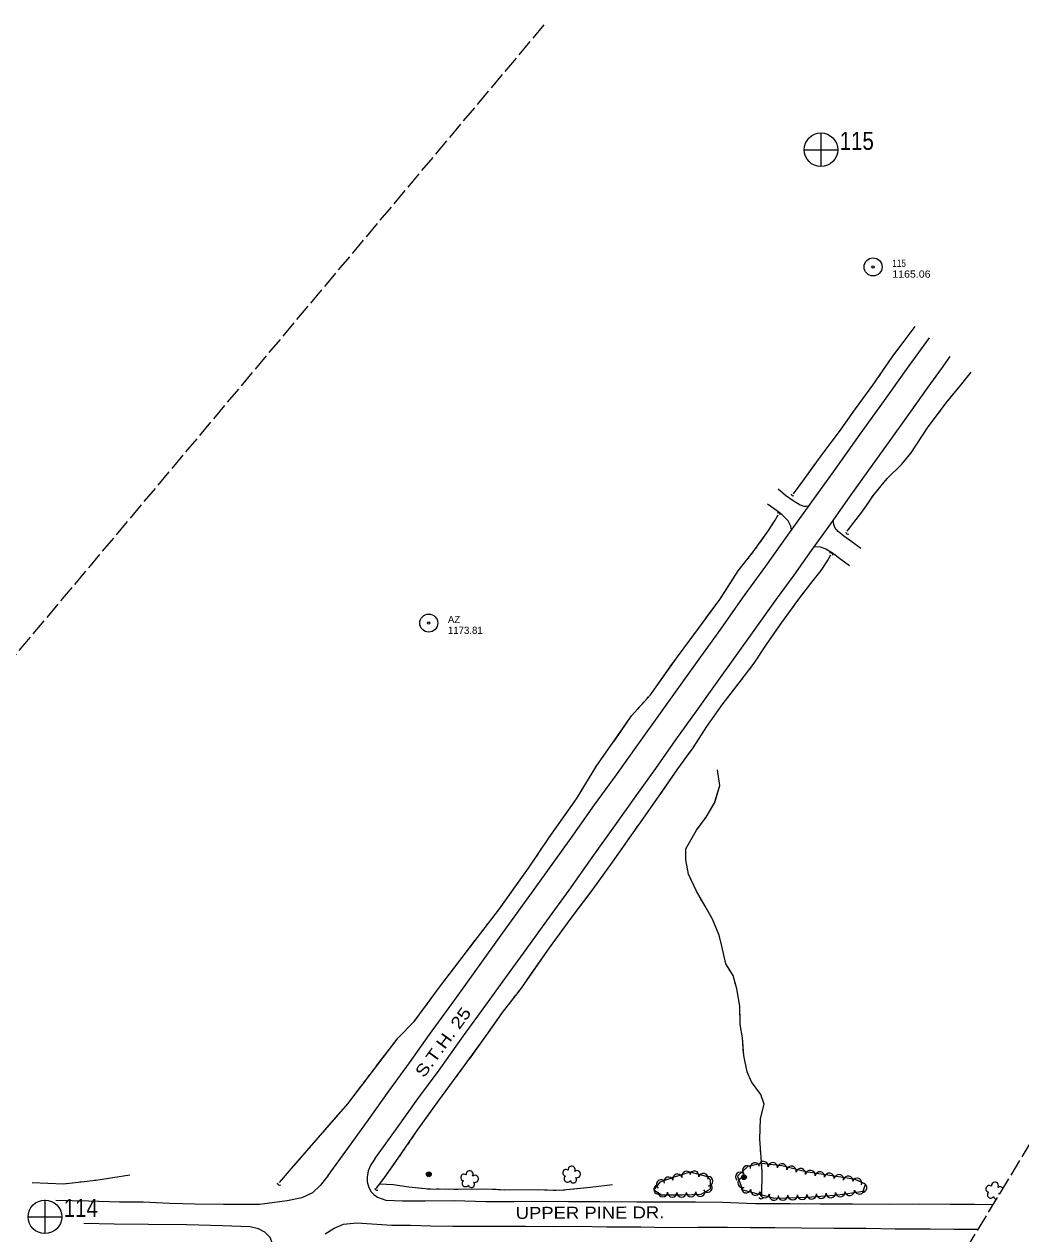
# Model space of a CAD drawing. Extents: x 299912 to 302269, y 50501 to 52727.
# Drawn here: x 300777 to 301607, y 51133 to 52140 of the extents above; entities that cross this region are included whole.
import ezdxf

# ---------------------------------------------------------------- set-up
doc = ezdxf.new("R2010")
doc.units = 0
doc.header["$LTSCALE"] = 2.4
doc.linetypes.add('LONG_DASHED', pattern=[7.5, 6, -1.5])
for name, color, linetype, lineweight in [('11', 7, 'Continuous', 25), ('14', 7, 'Continuous', 13), ('15', 7, 'Continuous', 13), ('17', 7, 'LONG_DASHED', 13), ('18', 7, 'Continuous', 13), ('19', 7, 'Continuous', 13), ('4', 7, 'Continuous', 13), ('6', 7, 'Continuous', 13)]:
    doc.layers.add(name, color=color, linetype=linetype, lineweight=lineweight)

msp = doc.modelspace()

# ---------------------------------------------------------------- linework, layer by layer
at = {"layer": '11'}
for points in [[(301030.007, 51181.149), (301047.014, 51204.403), (301063.672, 51227.601), (301080.566, 51251.235), (301097.734, 51274.915), (301114.585, 51298.443), (301135.571, 51327.45), (301153.998, 51353.028), (301175.685, 51383.222), (301194.525, 51409.49), (301211.625, 51433.285), (301232.183, 51461.909), (301252.093, 51489.845), (301270.355, 51515.057), (301288.212, 51539.974), (301306.971, 51566.236), (301323.759, 51589.729), (301339.213, 51611.228), (301357.233, 51636.354), (301375.434, 51662.035), (301394.708, 51688.805), (301413.138, 51714.567), (301431.636, 51740.489), (301452.429, 51769.443), (301473.451, 51798.854), (301493.551, 51826.891), (301511.926, 51852.541), (301531.073, 51879.143)], [(301068.854, 51194.99), (301086.974, 51220.113), (301104.786, 51244.929), (301122.378, 51268.943), (301142.82, 51297.37), (301161.297, 51323.08), (301179.46, 51347.984), (301195.045, 51369.431), (301212.341, 51393.305), (301230.758, 51418.776), (301250.082, 51446.051), (301268.963, 51472.323), (301286.717, 51497.399), (301303.095, 51520.241), (301319.863, 51544.01), (301336.981, 51567.976), (301351.404, 51588.279), (301370.357, 51614.741), (301386.323, 51637.108), (301403.784, 51661.391), (301418.292, 51681.277), (301432.749, 51701.911), (301448.871, 51724.104), (301463.212, 51744.317), (301479.209, 51766.758), (301496.984, 51791.456), (301514.628, 51815.931), (301530.056, 51837.899), (301541.095, 51853.142), (301548.391, 51863.553)], [(301068.854, 51194.99), (301065.444, 51189.953), (301063.437, 51184.92), (301062.592, 51179.821), (301062.381, 51175.94), (301063.58, 51171.87), (301065.5, 51167.886), (301067.97, 51165.401), (301071.23, 51163.033), (301074.098, 51162.001), (301077.997, 51160.671), (301092.055, 51160.116), (301110.856, 51159.999), (301135.177, 51160.188), (301161.367, 51159.458), (301185.028, 51159.394), (301208.788, 51159.576), (301230.116, 51159.482), (301256.401, 51159.431), (301287.257, 51159.108), (301312.985, 51159.252), (301336.181, 51159.101), (301358.657, 51158.812), (301386.076, 51157.897), (301414.94, 51157.726), (301439.969, 51157.378), (301466.928, 51157.513), (301497.572, 51157.317), (301523.037, 51157.547), (301548.404, 51157.168), (301568.532, 51157.153), (301584.04, 51157.001)], [(301030.007, 51181.149), (301023.253, 51172.718), (301017.043, 51166.584), (301008.163, 51162.486), (300995.866, 51160.121), (300972.836, 51157.009), (300942.884, 51156.811), (300919.181, 51157.333), (300897.924, 51157.791), (300875.705, 51158.909), (300856.054, 51158.98), (300830.211, 51159.603), (300802.901, 51160.158)], [(300937.665, 51052.35), (300948.96, 51067.795), (300962.34, 51086.522), (300973.837, 51102.347), (300980.826, 51112.339), (300983.524, 51117.902), (300983.699, 51124.492), (300981.529, 51129.444), (300977.355, 51133.747), (300971.926, 51136.725), (300965.099, 51138.361), (300942.042, 51139.1), (300912.271, 51139.909), (300880.328, 51140.137), (300851.613, 51140.546), (300826.248, 51141.024)], [(301027.487, 51132.484), (301035.101, 51137.124), (301042.714, 51140.527), (301053.832, 51141.717), (301070.425, 51140.556), (301082.862, 51139.682), (301098.541, 51139.579), (301115.587, 51139.262), (301133.98, 51138.959), (301155.725, 51139.01), (301173.969, 51138.84), (301194.485, 51138.925), (301217.475, 51138.683), (301238.152, 51138.78), (301262.162, 51138.455), (301290.563, 51138.275), (301313.431, 51137.861), (301337.789, 51137.928), (301362.93, 51137.939), (301381.996, 51137.771), (301402.223, 51137.859), (301424.429, 51137.516), (301451.548, 51137.112), (301478.4, 51137.154), (301502.642, 51136.595), (301531.587, 51136.55), (301551.826, 51136.439), (301571.518, 51136.387)]]:
    msp.add_lwpolyline(points, dxfattribs=at)
at = {"layer": '14'}
for centre, radius in [((301113.85, 51182.141), 2.018), ((301113.838, 51182.147), 1.518), ((301113.873, 51182.127), 1.008), ((301113.868, 51182.136), 0.502), ((301376.502, 51179.703), 2.018), ((301376.49, 51179.709), 1.518), ((301376.525, 51179.689), 1.008), ((301376.52, 51179.698), 0.502)]:
    msp.add_circle(centre, radius, dxfattribs=at)
at = {"layer": '15'}
for centre, radius, start, end in [((301417.578, 51749.26), 1.803, 184.36862, 290.60818), ((301404.821, 51731.319), 1.855, 4.88223, 111.1218), ((301463.173, 51717.358), 1.817, 184.27214, 290.51171), ((301448.525, 51697.901), 2.04, 4.49441, 110.73398), ((300989.781, 51175.348), 2.295, 186.25561, 292.49518), ((301070.67, 51170.633), 1.832, 182.56024, 288.7998), ((301390.989, 51164.055), 2.372, 209.35363, 315.59319)]:
    msp.add_arc(centre, radius, start, end, dxfattribs=at)
at = {"layer": '17'}
for points in [[(301404.91, 51753.214), (301411.012, 51748.014), (301417.539, 51743.527), (301423.306, 51740.024), (301426.521, 51738.909), (301428.262, 51738.88), (301430.681, 51739.151)], [(301416.104, 51718.723), (301415.587, 51722.216), (301413.326, 51726.549), (301408.449, 51731.612), (301403.696, 51735.293), (301396.168, 51740.426)], [(301474.029, 51703.408), (301466.45, 51708.994), (301459.792, 51713.789), (301454.976, 51717.791), (301452.277, 51721.069), (301451.302, 51723.498), (301451.001, 51727.107)], [(301435.156, 51705.224), (301439.996, 51704.803), (301444.756, 51703.158), (301450.39, 51699.995), (301457.172, 51694.626), (301464.351, 51689.387)]]:
    msp.add_lwpolyline(points, dxfattribs=at)
at = {"layer": '18'}
for points in [[(301428.219, 51184.021), (301408.042, 51189.031), (301391.174, 51191.136), (301379.762, 51188.531), (301371.027, 51180.507), (301375.319, 51169.195), (301402.093, 51162.251), (301429.118, 51163.082), (301451.908, 51164.736), (301461.046, 51165.728), (301475.847, 51167.989), (301477.689, 51174.007), (301469.18, 51177.815), (301460.863, 51179.272)], [(301331.755, 51183.846), (301318.456, 51179.677), (301306.324, 51175.553), (301301.506, 51169.217), (301307.732, 51165.104), (301325.015, 51164.869), (301340.746, 51165.56), (301348.652, 51170.07), (301348.752, 51177.208), (301346.514, 51179.799), (301343.475, 51180.866)]]:
    msp.add_lwpolyline(points, close=True, dxfattribs=at)
for centre, radius, start, end in [((301232.929, 51186.01), 2.974, 328.44813, 189.68202), ((301379.299, 51185.26), 4.004, 42.57835, 222.56303), ((301385.545, 51187.701), 4.004, 12.86617, 192.85084), ((301392.656, 51188.839), 4.004, 352.89435, 172.87903), ((301400.602, 51187.848), 4.004, 352.89435, 172.87903), ((301408.285, 51186.811), 4.004, 346.06299, 166.04767), ((301416.056, 51184.882), 4.004, 346.06299, 166.04767), ((301143.23, 51179.471), 2.777, 51.41902, 259.19202), ((301147.893, 51182.142), 2.974, 328.44813, 189.68202), ((301152.307, 51178.296), 2.975, 246.09895, 129.07222), ((301228.266, 51183.339), 2.777, 51.41902, 259.19202), ((301229.462, 51178.421), 2.783, 128.09604, 329.10709), ((301234.416, 51177.481), 2.611, 190.80419, 48.73679), ((301237.343, 51182.164), 2.975, 246.09895, 129.07222), ((301313.686, 51175.88), 3.936, 18.78197, 198.76665), ((301321.106, 51178.349), 3.936, 17.41294, 197.39762), ((301328.616, 51180.703), 3.936, 17.41294, 197.39762), ((301335.061, 51180.88), 3.936, 345.74159, 165.72627), ((301342.688, 51178.941), 3.936, 345.74159, 165.72627), ((301346.679, 51176.3), 3.936, 269.20503, 89.18971), ((301373.402, 51179.843), 4.004, 42.57835, 222.56303), ((301375.366, 51174.979), 4.004, 110.78541, 290.77009), ((301423.828, 51182.952), 4.004, 346.06299, 166.04767), ((301431.879, 51181.371), 4.004, 351.73043, 171.7151), ((301439.803, 51180.218), 4.004, 351.73043, 171.7151), ((301447.727, 51179.065), 4.004, 351.73043, 171.7151), ((301455.651, 51177.913), 4.004, 351.73043, 171.7151), ((301463.501, 51176.682), 4.004, 350.07122, 170.0559), ((301470.705, 51174.837), 4.004, 335.8979, 155.88258), ((301144.426, 51174.553), 2.783, 128.09604, 329.10709), ((301149.38, 51173.613), 2.611, 190.80419, 48.73679), ((301305.367, 51169.528), 3.936, 106.55824, 286.54292), ((301307.482, 51173.673), 3.936, 52.7577, 232.74238), ((301346.182, 51171.032), 3.936, 209.71038, 29.69506), ((301378.378, 51170.567), 4.004, 165.46801, 345.45269), ((301386.129, 51168.557), 4.004, 165.46801, 345.45269), ((301464.642, 51168.397), 4.004, 188.69302, 8.67769), ((301472.558, 51169.607), 4.004, 188.69302, 8.67769), ((301474.965, 51170.973), 4.004, 282.98927, 102.97394), ((301580.976, 51169.924), 2.777, 51.41902, 259.19202), ((301585.639, 51172.595), 2.974, 328.44813, 189.68202), ((301590.053, 51168.749), 2.975, 39.88291, 129.07222), ((301308.873, 51167.148), 3.936, 179.22865, 359.21333), ((301316.743, 51167.041), 3.936, 179.22865, 359.21333), ((301324.612, 51166.934), 3.936, 179.22865, 359.21333), ((301332.357, 51167.253), 3.936, 182.52282, 2.5075), ((301340.219, 51167.599), 3.936, 182.52282, 2.5075), ((301393.879, 51166.546), 4.004, 165.46801, 345.45269), ((301401.63, 51164.536), 4.004, 165.46801, 345.45269), ((301409.011, 51164.56), 4.004, 181.76891, 1.75359), ((301417.015, 51164.807), 4.004, 181.76891, 1.75359), ((301425.018, 51165.053), 4.004, 181.76891, 1.75359), ((301432.926, 51165.46), 4.004, 184.15866, 4.14334), ((301440.912, 51166.039), 4.004, 184.15866, 4.14334), ((301448.899, 51166.619), 4.004, 184.15866, 4.14334), ((301456.794, 51167.374), 4.004, 186.2033, 6.18797), ((301582.172, 51165.006), 2.783, 128.09604, 329.10709), ((301587.126, 51164.066), 2.611, 190.80419, 261.98746), ((301587.126, 51164.066), 2.611, 35.45675, 48.73679), ((301590.053, 51168.749), 2.975, 246.09895, 257.56129)]:
    msp.add_arc(centre, radius, start, end, dxfattribs=at)
at = {"layer": '19'}
for p, q in [((301493.02, 51852.803), (301494.239, 51854.579)), ((301496.677, 51858.131), (301497.896, 51859.907)), ((301489.363, 51847.474), (301490.582, 51849.25)), ((301538.974, 51816.656), (301540.238, 51818.337)), ((301542.765, 51821.701), (301544.028, 51823.383)), ((301535.184, 51811.61), (301536.448, 51813.292)), ((301442.6, 51782.938), (301443.887, 51784.665)), ((301446.461, 51788.12), (301447.748, 51789.848)), ((301438.764, 51777.736), (301440.036, 51779.475)), ((301490.957, 51755.731), (301492.306, 51757.344)), ((301483.097, 51745.876), (301484.273, 51747.618)), ((301486.908, 51750.892), (301488.257, 51752.505)), ((301386.324, 51703.519), (301387.436, 51705.098)), ((301379.248, 51694.344), (301380.455, 51695.852)), ((301382.87, 51698.867), (301384.078, 51700.375)), ((301424.675, 51664.554), (301425.913, 51666.167)), ((301428.387, 51669.392), (301429.624, 51671.005)), ((301421.039, 51659.66), (301422.225, 51661.311)), ((301341.407, 51640.717), (301342.554, 51642.272)), ((301334.501, 51631.406), (301335.655, 51632.956)), ((301299.465, 51582.831), (301315.648, 51605.704)), ((301381.382, 51603.09), (301382.623, 51604.7)), ((301373.936, 51593.431), (301375.177, 51595.041)), ((301377.659, 51598.26), (301378.9, 51599.87)), ((301291.864, 51574.091), (301293.156, 51575.527)), ((301295.74, 51578.401), (301297.032, 51579.837)), ((301287.988, 51569.78), (301289.28, 51571.217)), ((301330.34, 51532.196), (301331.537, 51533.839)), ((301326.749, 51527.268), (301327.946, 51528.911)), ((301246.941, 51511.362), (301247.936, 51513.018)), ((301249.927, 51516.329), (301250.922, 51517.985)), ((301243.955, 51506.395), (301244.95, 51508.05)), ((301346.697, 51482.534), (301347.641, 51484.17)), ((301349.53, 51487.442), (301350.474, 51489.078)), ((301287.007, 51470.741), (301288.175, 51472.404)), ((301343.62, 51477.788), (301344.756, 51479.297)), ((301280.002, 51460.761), (301281.169, 51462.425)), ((301283.505, 51465.751), (301284.672, 51467.414)), ((301207.039, 51452.095), (301208.114, 51453.7)), ((301200.583, 51442.467), (301201.659, 51444.071)), ((301203.811, 51447.281), (301204.887, 51448.886)), ((301336.075, 51419.707), (301335.275, 51421.417)), ((301338.75, 51414.716), (301337.809, 51416.354)), ((301341.573, 51409.802), (301340.632, 51411.44)), ((301235.894, 51399.876), (301237.115, 51401.5)), ((301239.557, 51404.748), (301240.779, 51406.373)), ((301161.969, 51389.338), (301163.14, 51390.875)), ((301232.247, 51394.99), (301233.452, 51396.627)), ((301154.943, 51380.117), (301156.114, 51381.654)), ((301158.456, 51384.727), (301159.627, 51386.264)), ((301195.639, 51343.723), (301212.442, 51367.933)), ((301365.473, 51350.838), (301364.479, 51352.444)), ((301192.162, 51338.714), (301193.321, 51340.384)), ((301367.959, 51345.804), (301367.456, 51347.624)), ((301369.466, 51340.343), (301368.964, 51342.164)), ((301184.729, 51329.059), (301185.982, 51330.658)), ((301188.487, 51333.855), (301189.74, 51335.454)), ((301108.402, 51318.431), (301109.546, 51319.987)), ((301111.835, 51323.1), (301112.979, 51324.656)), ((301115.268, 51327.769), (301116.412, 51329.325)), ((301070.318, 51272.376), (301087.393, 51294.58)), ((301140.502, 51268.298), (301141.709, 51269.933)), ((301144.118, 51273.205), (301145.313, 51274.848)), ((301377.276, 51276.815), (301376.87, 51278.66)), ((301378.494, 51271.281), (301378.088, 51273.126)), ((301059.751, 51258.571), (301060.924, 51260.106)), ((301063.269, 51263.176), (301064.441, 51264.711)), ((301136.883, 51263.394), (301138.089, 51265.029)), ((301380.023, 51265.844), (301379.308, 51267.592)), ((301021.67, 51212.383), (301039.96, 51233.601)), ((301096.582, 51207.307), (301097.729, 51208.983)), ((301010.291, 51199.235), (301011.556, 51200.695)), ((301014.088, 51203.614), (301015.353, 51205.074)), ((301089.702, 51197.254), (301090.849, 51198.929)), ((301093.142, 51202.28), (301094.289, 51203.956)), ((301390.095, 51205.686), (301389.952, 51207.569)), ((301390.527, 51200.037), (301390.383, 51201.92)), ((301390.958, 51194.388), (301390.814, 51196.271)), ((300817.015, 51175.056), (300819.055, 51175.288)), ((300823.136, 51175.751), (300825.176, 51175.982)), ((300829.257, 51176.445), (300831.297, 51176.676)), ((301120.198, 51169.897), (301122.63, 51169.882)), ((301127.494, 51169.851), (301129.927, 51169.835)), ((301210.17, 51169.08), (301212.6, 51169.017)), ((301217.459, 51168.893), (301219.889, 51168.83)), ((301224.738, 51168.914), (301227.151, 51169.172))]:
    msp.add_line(p, q, dxfattribs=at)
for points in [[(301417.935, 51748.937), (301426.349, 51760.761), (301440.899, 51780.655), (301457.447, 51802.865), (301469.365, 51819.834), (301483.942, 51839.575), (301499.994, 51862.965), (301510.103, 51876.365), (301519.094, 51888.425)], [(301500.355, 51863.444), (301510.103, 51876.365), (301519.094, 51888.425)], [(301462.635, 51717.891), (301475.648, 51734.836), (301484.709, 51748.264), (301495.998, 51761.756), (301508.13, 51773.69), (301515.818, 51783.211), (301529.456, 51803.985), (301545.058, 51824.754), (301558.037, 51840.806), (301565.774, 51850.43)], [(301468.547, 51818.669), (301469.365, 51819.834), (301483.942, 51839.575), (301486.925, 51843.922)], [(301546.625, 51826.692), (301558.037, 51840.806), (301565.774, 51850.43)], [(301450.322, 51793.303), (301457.447, 51802.865), (301468.547, 51818.669)], [(301515.621, 51782.966), (301515.818, 51783.211), (301529.456, 51803.985), (301532.657, 51808.246)], [(301417.935, 51748.937), (301426.349, 51760.761), (301436.221, 51774.258)], [(301495.005, 51760.57), (301495.998, 51761.756), (301508.13, 51773.69), (301515.621, 51782.966)], [(301462.635, 51717.891), (301475.648, 51734.836), (301480.746, 51742.391)], [(300989.393, 51175.16), (300999.521, 51186.814), (301018.108, 51208.251), (301046.288, 51240.942), (301066.826, 51267.834), (301088.285, 51295.74), (301101.716, 51309.337), (301124.372, 51340.151), (301145.396, 51367.586), (301172.671, 51403.384), (301197.002, 51437.125), (301214.19, 51462.762), (301237.092, 51494.977), (301253.783, 51522.745), (301267.096, 51541.255), (301282.839, 51564.054), (301298.509, 51581.48), (301321.055, 51613.347), (301338.646, 51636.973), (301356.39, 51661.034), (301371.726, 51684.952), (301384.334, 51700.695), (301396.844, 51718.451), (301402.408, 51727.16), (301405.06, 51731.637)], [(301389.662, 51708.258), (301396.844, 51718.451), (301402.408, 51727.16), (301405.06, 51731.637)], [(301069.98, 51170.169), (301076.7, 51178.974), (301089.007, 51196.238), (301103.695, 51217.701), (301122.26, 51243.581), (301143.731, 51272.673), (301160.104, 51295.189), (301175.27, 51316.988), (301191.135, 51337.234), (301214.333, 51370.657), (301233.488, 51396.676), (301250.468, 51419.259), (301267.103, 51442.289), (301279.522, 51460.078), (301292.157, 51478.076), (301306.48, 51498.188), (301321.488, 51520.047), (301334.224, 51537.527), (301345.625, 51555.147), (301358.423, 51573.295), (301372.412, 51591.454), (301385.118, 51607.937), (301395.191, 51623.572), (301408.16, 51641.722), (301422.763, 51662.061), (301434.126, 51676.873), (301440.896, 51685.261), (301446.045, 51693.15), (301449.019, 51698.266)], [(301432.098, 51674.23), (301434.126, 51676.873), (301440.896, 51685.261), (301446.045, 51693.15), (301449.019, 51698.266)], [(301361.015, 51668.247), (301371.726, 51684.952), (301376.833, 51691.329)], [(301344.847, 51645.382), (301356.39, 51661.034), (301361.015, 51668.247)], [(301401.5, 51632.402), (301408.16, 51641.722), (301418.668, 51656.358)], [(301337.963, 51636.055), (301338.646, 51636.973), (301339.113, 51637.607)], [(301385.105, 51607.92), (301385.118, 51607.937), (301395.191, 51623.572), (301401.5, 51632.402)], [(301315.648, 51605.704), (301321.055, 51613.347), (301332.194, 51628.307)], [(301353.743, 51566.659), (301358.423, 51573.295), (301371.454, 51590.211)], [(301269.1, 51544.157), (301282.839, 51564.054), (301285.405, 51566.907)], [(301337.266, 51542.229), (301345.625, 51555.147), (301353.743, 51566.659)], [(301252.912, 51521.297), (301253.783, 51522.745), (301267.096, 51541.255), (301269.1, 51544.157)], [(301333.931, 51537.125), (301334.224, 51537.527), (301335.058, 51538.816)], [(301307.563, 51499.766), (301321.488, 51520.047), (301324.355, 51523.982)], [(301391.419, 51163.261), (301391.702, 51184.645), (301389.654, 51211.468), (301390.421, 51228.477), (301393.467, 51240.507), (301390.728, 51248.453), (301382.75, 51259.185), (301379.303, 51267.604), (301376.307, 51281.219), (301375.43, 51295.892), (301373.319, 51307.022), (301373.029, 51322.05), (301370.494, 51336.619), (301367.453, 51347.637), (301361.31, 51357.567), (301358.103, 51372.064), (301355.857, 51381.235), (301350.422, 51394.588), (301344.082, 51405.434), (301336.922, 51417.898), (301330.21, 51432.238), (301327.969, 51444.037), (301327.998, 51453.374), (301336.883, 51468.837), (301345.069, 51479.713), (301352.148, 51491.979), (301356.302, 51505.99), (301354.563, 51519.078)], [(301352.27, 51492.39), (301356.302, 51505.99), (301354.563, 51519.078)], [(301226.34, 51479.853), (301237.092, 51494.977), (301241.965, 51503.083)], [(301290.51, 51475.73), (301292.157, 51478.076), (301306.48, 51498.188), (301307.563, 51499.766)], [(301210.266, 51456.909), (301214.19, 51462.762), (301226.34, 51479.853)], [(301327.991, 51451.246), (301327.998, 51453.374), (301336.883, 51468.837), (301341.349, 51474.77)], [(301260.662, 51433.371), (301267.103, 51442.289), (301277.674, 51457.43)], [(301333.673, 51424.839), (301330.21, 51432.238), (301327.969, 51444.037), (301327.991, 51451.246)], [(301182.119, 51416.485), (301197.002, 51437.125), (301198.431, 51439.257)], [(301243.221, 51409.621), (301250.468, 51419.259), (301260.662, 51433.371)], [(301165.482, 51393.949), (301172.671, 51403.384), (301182.119, 51416.485)], [(301355.536, 51382.024), (301350.422, 51394.588), (301344.082, 51405.434), (301343.455, 51406.526)], [(301212.442, 51367.933), (301214.333, 51370.657), (301229.837, 51391.717)], [(301362.492, 51355.656), (301361.31, 51357.567), (301358.103, 51372.064), (301355.857, 51381.235), (301355.536, 51382.024)], [(301135.587, 51354.786), (301145.396, 51367.586), (301152.602, 51377.043)], [(301118.701, 51332.438), (301124.372, 51340.151), (301135.587, 51354.786)], [(301373.27, 51309.539), (301373.029, 51322.05), (301370.494, 51336.619), (301370.471, 51336.703)], [(301164.886, 51302.062), (301175.27, 51316.988), (301182.224, 51325.862)], [(301087.393, 51294.58), (301088.285, 51295.74), (301101.716, 51309.337), (301106.114, 51315.318)], [(301147.702, 51278.134), (301160.104, 51295.189), (301164.886, 51302.062)], [(301376.238, 51282.375), (301375.43, 51295.892), (301373.319, 51307.022), (301373.27, 51309.539)], [(301066.786, 51267.782), (301066.826, 51267.834), (301067.963, 51269.313)], [(301117.073, 51236.351), (301122.26, 51243.581), (301134.47, 51260.125)], [(301392.93, 51238.387), (301393.467, 51240.507), (301390.728, 51248.453), (301382.75, 51259.185), (301381.454, 51262.349)], [(301039.96, 51233.601), (301046.288, 51240.942), (301057.407, 51255.5)], [(301100.022, 51212.334), (301103.695, 51217.701), (301117.073, 51236.351)], [(301389.664, 51211.335), (301389.654, 51211.468), (301390.421, 51228.477), (301392.93, 51238.387)], [(301017.885, 51207.993), (301018.108, 51208.251), (301019.147, 51209.456)], [(300989.393, 51175.16), (300999.521, 51186.814), (301007.759, 51196.315)], [(301069.98, 51170.169), (301076.7, 51178.974), (301087.363, 51193.932)], [(301391.419, 51163.261), (301391.702, 51184.645), (301391.246, 51190.622)], [(300783.186, 51175.295), (300809.536, 51174.208), (300836.337, 51177.248), (300864.798, 51181.535)], [(300835.377, 51177.139), (300836.337, 51177.248), (300864.798, 51181.535)], [(300783.186, 51175.295), (300809.536, 51174.208), (300812.934, 51174.593)], [(301073.016, 51174.147), (301084.153, 51173.476), (301097.236, 51171.739), (301114.026, 51169.936), (301138.224, 51169.783), (301162.016, 51169.922), (301176.741, 51169.282), (301198.5, 51169.379), (301223.169, 51168.746), (301248.433, 51171.448), (301266.917, 51173.574)], [(301073.016, 51174.147), (301084.153, 51173.476), (301097.236, 51171.739), (301108.072, 51170.575)], [(301112.908, 51170.056), (301114.026, 51169.936), (301115.333, 51169.928)], [(301134.791, 51169.805), (301138.224, 51169.783), (301162.016, 51169.922), (301170.054, 51169.573)], [(301170.054, 51169.573), (301176.741, 51169.282), (301198.5, 51169.379), (301205.31, 51169.204)], [(301231.977, 51169.688), (301248.433, 51171.448), (301266.917, 51173.574)]]:
    msp.add_lwpolyline(points, dxfattribs=at)
at = {"layer": '4', "linetype": 'LONG_DASHED'}
for p, q in [((300552.76, 51356.525), (301210.553, 52140.364)), ((301858.628, 51609.011), (301331.18, 50740.757))]:
    msp.add_line(p, q, dxfattribs=at)
at = {"layer": '4'}
for p, q in [((301440.629, 52049.754), (301440.564, 52021.9)), ((301426.72, 52035.724), (301454.625, 52035.711)), ((300793.889, 51160.689), (300793.824, 51132.835)), ((300779.98, 51146.659), (300807.885, 51146.646))]:
    msp.add_line(p, q, dxfattribs=at)
for centre in [(301440.681, 52035.732), (300793.941, 51146.667)]:
    msp.add_circle(centre, 14, dxfattribs=at)
at = {"layer": '6'}
for centre, radius in [((301484.128, 51938.166), 7.5), ((301484.128, 51938.166), 0.96), ((301113.806, 51641.369), 7.5), ((301113.806, 51641.369), 0.96)]:
    msp.add_circle(centre, radius, dxfattribs=at)

# ---------------------------------------------------------------- texts
at = {"layer": '11'}
for s, rotation, width, p in [('S.T.H. 25', 53.775, 1.2, (301109.767, 51261.881)), ('UPPER PINE DR.', 0.237, 1.15, (301186.299, 51144.891))]:
    msp.add_text(s, height=10, rotation=rotation, dxfattribs=dict(at, width=width)).set_placement(p)
at = {"layer": '4', "width": 0.85}
for s, p in [('115', (301456.333, 52035.662)), ('114', (300809.593, 51146.597))]:
    msp.add_text(s, height=15, dxfattribs=at).set_placement(p)
at = {"layer": '6'}
for s, width, p in [('115', 0.85, (301500.128, 51938.166)), ('1165.06', 1.1, (301500.128, 51929.166))]:
    msp.add_text(s, height=6, dxfattribs=dict(at, width=width)).set_placement(p)
for s, p in [('AZ', (301129.806, 51641.369)), ('1173.81', (301129.806, 51632.369))]:
    msp.add_text(s, height=6, dxfattribs=at).set_placement(p)

doc.saveas('drawing.dxf')
